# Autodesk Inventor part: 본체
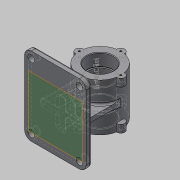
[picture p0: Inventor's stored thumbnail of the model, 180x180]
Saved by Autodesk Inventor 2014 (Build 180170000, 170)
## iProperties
Created: 2015-12
Part Number: 본체
Material: Generic
Document SubType Name: Modeling
Designer: user
Density: 1 g/cm^3
Appearance: Default
Mass: 427.799 g
Surface Area: 820.957 cm^2
Volume: 427.799 cm^3
Author: user
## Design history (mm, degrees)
sketch "Sketch11"
  geometry: C1 r 37 at (0, 0); 1 further point
  constraints: 1 centre point, 1 coincident
  dimensions: "d43" = 74 diameter of C1
extrude "Extrusion3" new body sketch "Sketch11" stored distance "d44" = 85; taper "d45" = 0 deg
sketch "Sketch12"
  geometry: L1 (37, -42.5)-(37, 42.5) reference; L2 (37, 42.5)-(37, 27.5); L3 (37, 42.5)-(44, 42.5); L4 (44, 42.5)-(44, 28.734); L5 (37, 27.5)-(44, 28.734); 1 further point
  constraints: 8 end point, 2 perpendicular, 1 point on line
  dimensions: "d46" = 15 distance of L1.end L2.end; "d47" = 7 distance of L1.end L3.end; "d48" = 80 deg angle of L2 L5
revolve "Revolution3" sketch "Sketch12" stored, may be unused: angle "d49" = 90 deg
pattern_circular "Circular Pattern2" dims angle "d51" = 360 deg
mirror "Mirror2"
workplane "Work Plane3"
sketch "Sketch14"
  geometry: L1 (55, -60)-(-55, -60); L2 (-55, -60)-(-55, 80); L3 (-55, 80)-(55, 80); L4 (55, 80)-(55, -60); 1 further point
  constraints: 8 end point, 2 parallel, 1 horizontal, 1 perpendicular
  dimensions: "d55" = 110 distance of L1.start L1.end; "d56" = 140 distance of L1.end L2.end; "d57" = 60 distance from line of L1 point (0, 0); "d58" = 55 distance from line of L2 point (0, 0)
extrude "Extrusion4" join sketch "Sketch14" distance "d59" = 10; taper "d60" = 0 deg
sketch "Sketch15"
  geometry: L1 (37, 0)-(37, -70); L2 (-37, 0)-(-37, -70); A1 r 37 centre (0, 0) between (6.969, -36.338) and (36.338, -6.969) reference; A2 r 37 centre (0, 0) between (-37, 0) and (37, 0); 1 further point
  constraints: 4 end point, 2 point on circle, 1 centre point, 1 coincident
feature "Rib1" sketch "Sketch15" dims "d62" = 1, "d63" = 8, "d64" = 0, "d65" = 0, "d66" = 1, "d67" = 1
sketch "Sketch17"
  geometry: L1 (-70, 18)-(-70, -25); L2 (-70, -25)-(-70, 25); L3 (0, -4)-(0, 4) reference; L4 (-70, 80)-(-70, -60) reference; L5 (-70, -25)-(-28.538, -19.909); L6 (-70, 25)-(-28.538, 19.909); L7 (-28.538, 19.909)-(-28.538, -19.909); 3 further points
  constraints: 10 end point, 2 midpoint, 1 collinear, 1 horizontal alignment, 1 parallel, 1 vertical
  dimensions: "d72" = 50 distance of L1.end L2.end; "d73" = 70 distance between parallel lines of L1 L3; "d74" = 97 deg angle of L1 L5; "d75" = 97 deg angle of L2 L6
extrude "Extrusion5" join sketch "Sketch17" stored distance "d76" = 12; taper "d77" = 0 deg
hole "Hole1" diameter "d80" = 47; stored, may be unused: countersink angle "d84" = 90 deg, drill point angle "d86" = 0 deg; dims "d78" = 10, "d79" = 10, "d81" = 6, "d82" = 4, "d83" = 2, "d85" = 22
sketch "Sketch18"
  geometry: C1 r 21 at (0, 0); 1 further point
  constraints: 1 centre point, 1 coincident
  dimensions: "d87" = 42 diameter of C1
extrude "Extrusion6" cut sketch "Sketch18" distance "d88" = 20.5; taper "d89" = 0 deg
mirror "Mirror3"
fillet "Fillet1" dims "d90" = 12
hole "Hole2" diameter "d93" = 12; stored, may be unused: countersink angle "d97" = 90 deg, drill point angle "d99" = 0 deg; dims "d91" = 10, "d92" = 10, "d94" = 6, "d95" = 4, "d96" = 2, "d98" = 22
pattern_linear "Rectangular Pattern1" dims "d102" = 116, "d105" = 86
sketch "Sketch19"
  geometry: A1 r 7 centre (37, 0) between (36.338, -6.969) and (36.338, 6.969) reference
hole "Hole3" sketch "Sketch19" at (37, 0) diameter "d106" = 3.242; stored, may be unused: countersink angle "d110" = 90 deg, drill point angle "d112" = 0 deg; dims "d107" = 9, "d108" = 4, "d109" = 2, "d111" = 11
pattern_circular "Circular Pattern3" dims angle "d114" = 360 deg
mirror "Mirror4"
chamfer "Chamfer1" distance "d116" = 1; stored, may be unused: second distance "d117" = 2, angle "d118" = 45 deg
chamfer "Chamfer2" distance "d119" = 1; stored, may be unused: second distance "d120" = 2, angle "d121" = 45 deg
fillet "Fillet2" dims "d122" = 0.3
fillet "Fillet3" dims "d123" = 3
fillet "Fillet4" dims "d124" = 3
sketch "Sketch20"
  geometry: L1 (0, 0)-(-40.2, 40.2); L2 (0, 0)-(-18, 0)
  constraints: 4 end point, 1 horizontal
  dimensions: "d125" = 45 deg angle of L2 L1
workplane "Work Plane4"
sketch "Sketch21"
  geometry: L1 (-7.476, -44.75)-(-7.476, 44.713); L2 (-7.476, 44.713)-(16.412, 44.713); L3 (16.412, 44.713)-(16.412, -44.75); L4 (16.412, -44.75)-(-7.476, -44.75); 1 further point
  constraints: 2 other
emboss "Emboss1" sketch "Sketch21" dims "d45" = 0, "d55" = 110, "d56" = 140, "d57" = 60, "d58" = 55, "d126" = 0.5, "d127" = 0
body "Solid2"
